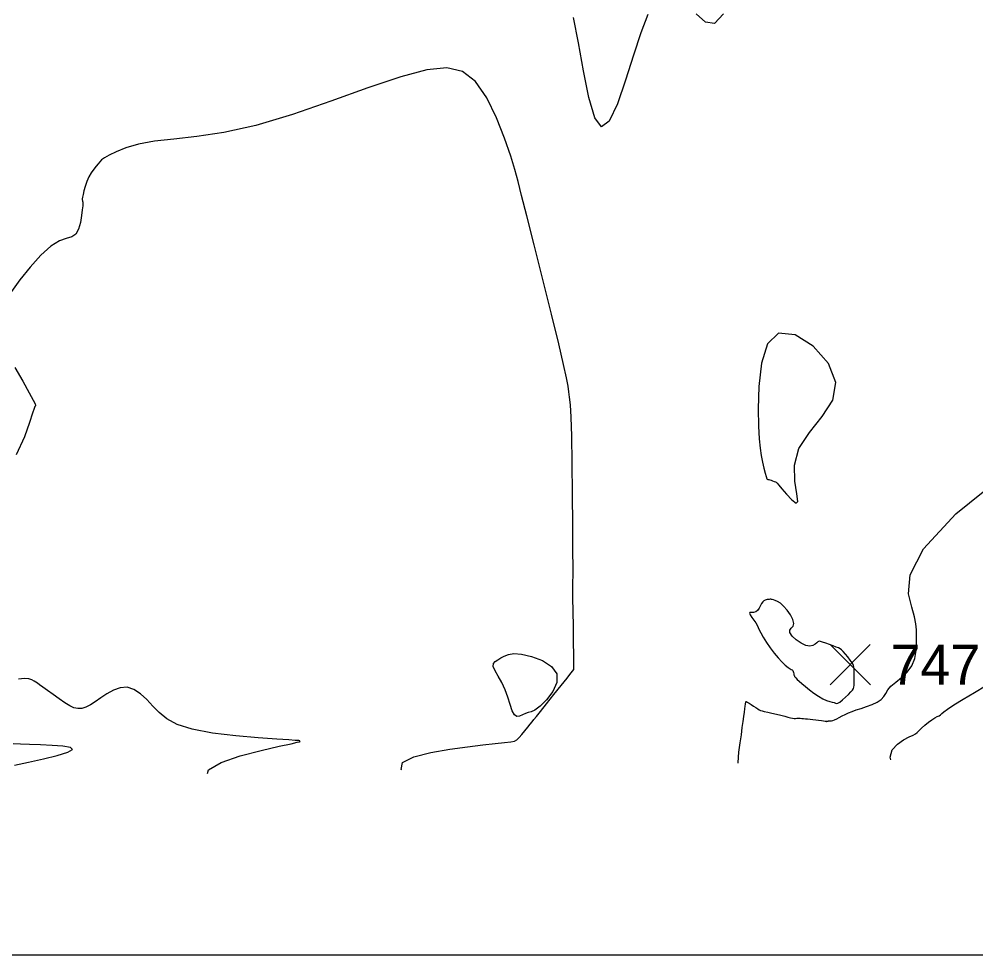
# Model space of a CAD drawing. Extents: x 2566142 to 2571431, y 418755 to 421584.
# Drawn here: x 2568478.9 to 2568835.3, y 418777.5 to 419126 of the extents above; entities that cross this region are included whole.
import ezdxf

# ---------------------------------------------------------------- set-up
doc = ezdxf.new("R2010")
doc.units = 0
for name, color, linetype in [('Contour_ADS_Major', 7, 'Continuous'), ('Contour_ADS_Minor', 7, 'Continuous'), ('Contour_ADS_Spot_Elevation', 7, 'Continuous'), ('Contour_ADS_State_Plane_Border', 7, 'Continuous')]:
    doc.layers.add(name, color=color, linetype=linetype)

# ---------------------------------------------------------------- blocks, each defined once
blk = doc.blocks.new('S750')
at = {"layer": 'Contour_ADS_Spot_Elevation'}
for p, q in [((-0.5, 0.498), (0.5, -0.498)), ((-0.498, -0.5), (0.498, 0.5))]:
    blk.add_line(p, q, dxfattribs=at)

msp = doc.modelspace()

# ---------------------------------------------------------------- linework, layer by layer
at = {"layer": 'Contour_ADS_Major'}
msp.add_lwpolyline([(2568477.19, 418848.2), (2568482.38, 418849.31), (2568487.94, 418850.54), (2568493.08, 418851.8), (2568496.98, 418852.98), (2568498.8, 418853.97), (2568498.01, 418854.69), (2568495.18, 418855.16), (2568491.15, 418855.47), (2568486.79, 418855.66), (2568482.81, 418855.81), (2568479.42, 418855.95), (2568476.7, 418856.09)], dxfattribs=at)
at = {"layer": 'Contour_ADS_Minor'}
for points in [[(2568713.02, 419127.71), (2568710.51, 419120.89), (2568707.78, 419112.58), (2568704.81, 419103.24), (2568701.72, 419094.43), (2568698.67, 419088.02), (2568695.84, 419085.87), (2568693.34, 419089.2), (2568691.13, 419096.77), (2568689.13, 419106.71), (2568687.25, 419117.14), (2568685.41, 419126.55)], [(2568741.27, 419127.97), (2568737.96, 419124.32), (2568734.53, 419124.89), (2568731.13, 419127.95)], [(2568621.43, 418846.45), (2568621.24, 418846.59), (2568621.73, 418849.14), (2568625.9, 418851.19), (2568632.28, 418852.81), (2568639.38, 418854.06), (2568645.93, 418855), (2568651.59, 418855.7), (2568656.22, 418856.19), (2568659.7, 418856.55), (2568661.99, 418856.82), (2568663.38, 418857.13), (2568664.29, 418857.61), (2568665.09, 418858.39), (2568666.09, 418859.54), (2568667.23, 418860.9), (2568668.35, 418862.28), (2568669.29, 418863.45), (2568669.99, 418864.31), (2568670.65, 418865.13), (2568671.6, 418866.3), (2568673.12, 418868.19), (2568675.39, 418871.03), (2568678.09, 418874.42), (2568680.78, 418877.79), (2568683.01, 418880.57), (2568684.43, 418882.35), (2568685.17, 418883.28), (2568685.45, 418883.64), (2568685.51, 418883.73), (2568685.52, 418883.85), (2568685.52, 418884.48), (2568685.51, 418886.08), (2568685.47, 418889.16), (2568685.41, 418893.95), (2568685.33, 418899.72), (2568685.25, 418905.5), (2568685.19, 418910.31), (2568685.15, 418913.44), (2568685.14, 418915.12), (2568685.14, 418915.89), (2568685.16, 418916.24), (2568685.19, 418916.74), (2568685.21, 418918.26), (2568685.22, 418921.69), (2568685.2, 418927.95), (2568685.14, 418937.5), (2568685.04, 418949.01), (2568684.9, 418960.68), (2568684.72, 418970.73), (2568684.5, 418977.8), (2568684.24, 418982.32), (2568683.96, 418985.17), (2568683.68, 418987.2), (2568683.36, 418989.29), (2568682.79, 418992.35), (2568681.72, 418997.32), (2568679.88, 419005.1), (2568677.15, 419016.16), (2568673.92, 419029.05), (2568670.68, 419041.89), (2568667.95, 419052.77), (2568666.08, 419060.35), (2568664.77, 419065.57), (2568663.57, 419069.93), (2568662.01, 419074.92), (2568659.73, 419081.6), (2568656.72, 419089.24), (2568653.07, 419096.67), (2568648.86, 419102.71), (2568644.08, 419106.42), (2568638.24, 419107.81), (2568630.75, 419107.09), (2568621.05, 419104.49), (2568608.83, 419100.35), (2568594.97, 419095.39), (2568580.67, 419090.44), (2568567.09, 419086.35), (2568555.2, 419083.71), (2568545.05, 419082.22), (2568536.47, 419081.34), (2568529.3, 419080.54), (2568523.4, 419079.4), (2568518.67, 419078.01), (2568515.02, 419076.57), (2568512.4, 419075.28), (2568510.68, 419074.31), (2568509.62, 419073.55), (2568508.93, 419072.87), (2568508.31, 419072.13), (2568507.56, 419071.22), (2568506.69, 419070.1), (2568505.77, 419068.77), (2568504.9, 419067.22), (2568504.14, 419065.48), (2568503.52, 419063.69), (2568503.04, 419062.02), (2568502.7, 419060.64), (2568502.5, 419059.67), (2568502.42, 419059.06), (2568502.42, 419058.69)], [(2568502.42, 419058.69), (2568502.45, 419058.46), (2568502.48, 419058.29), (2568502.51, 419058.14), (2568502.54, 419058.01), (2568502.58, 419057.88), (2568502.61, 419057.71), (2568502.61, 419057.32), (2568502.56, 419056.49), (2568502.43, 419055.02), (2568502.18, 419052.81), (2568501.74, 419050.22), (2568501.03, 419047.75), (2568499.96, 419045.87), (2568498.46, 419044.89), (2568496.46, 419044.29), (2568493.91, 419043.38), (2568490.75, 419041.46), (2568486.99, 419038.06), (2568483, 419033.65), (2568479.2, 419028.89), (2568476.03, 419024.49)], [(2568477.27, 418996.23), (2568480.21, 418991.12), (2568482.63, 418986.86), (2568484.13, 418984.12), (2568484.85, 418982.68), (2568485.04, 418982.09), (2568484.95, 418981.92), (2568484.78, 418981.73), (2568484.45, 418980.99), (2568483.81, 418979.18), (2568482.72, 418975.76), (2568480.92, 418970.41), (2568477.81, 418963.68)], [(2568813.11, 418898.58), (2568812.93, 418900.76), (2568812.42, 418903.38), (2568811.41, 418906.94), (2568810.16, 418911.94), (2568810.76, 418918.99), (2568815.8, 418928.71), (2568827.81, 418941.71), (2568848.18, 418958.1)], [(2568765.95, 418897.5), (2568765.96, 418898.41), (2568766.51, 418899.13), (2568767.17, 418899.89), (2568767.48, 418900.93), (2568767.12, 418902.41), (2568766.2, 418904.15), (2568764.96, 418905.89), (2568763.64, 418907.4), (2568762.44, 418908.46), (2568761.41, 418909.14), (2568760.56, 418909.52), (2568759.9, 418909.73), (2568759.43, 418909.84), (2568759.1, 418909.89), (2568758.84, 418909.91), (2568758.59, 418909.91), (2568758.28, 418909.9), (2568757.93, 418909.88), (2568757.55, 418909.84), (2568757.14, 418909.76), (2568756.73, 418909.63), (2568756.31, 418909.39), (2568755.88, 418908.99), (2568755.45, 418908.39), (2568755, 418907.55), (2568754.51, 418906.63), (2568753.94, 418905.8), (2568753.25, 418905.23), (2568752.45, 418905.04), (2568751.68, 418905.06), (2568751.1, 418905.06), (2568750.89, 418904.81), (2568751.17, 418904.16), (2568751.79, 418903.2), (2568752.56, 418902.13), (2568753.25, 418901.1), (2568753.75, 418900.25), (2568754.12, 418899.46), (2568754.55, 418898.56), (2568755.16, 418897.37), (2568756.1, 418895.77), (2568757.29, 418893.88), (2568758.67, 418891.87), (2568760.15, 418889.9), (2568761.63, 418888.13), (2568763.04, 418886.61), (2568764.29, 418885.39), (2568765.31, 418884.52), (2568766.04, 418884.01), (2568766.52, 418883.75), (2568766.83, 418883.59), (2568767.04, 418883.39), (2568767.2, 418883.06), (2568767.33, 418882.63), (2568767.44, 418882.19), (2568767.52, 418881.82), (2568767.58, 418881.59), (2568767.62, 418881.47), (2568767.65, 418881.42), (2568767.67, 418881.39), (2568767.69, 418881.32), (2568767.75, 418881.2), (2568767.92, 418880.98), (2568768.24, 418880.62), (2568768.76, 418880.1), (2568769.5, 418879.4), (2568770.49, 418878.52), (2568771.75, 418877.47), (2568773.28, 418876.25), (2568774.97, 418874.98), (2568776.68, 418873.79), (2568778.29, 418872.84), (2568779.68, 418872.21), (2568780.84, 418871.83), (2568781.77, 418871.61), (2568782.47, 418871.45), (2568782.98, 418871.27), (2568783.41, 418871.16), (2568783.89, 418871.25), (2568784.57, 418871.64), (2568785.53, 418872.42), (2568786.66, 418873.44), (2568787.77, 418874.51), (2568788.7, 418875.45), (2568789.32, 418876.13), (2568789.67, 418876.66), (2568789.84, 418877.22), (2568789.89, 418877.98), (2568789.91, 418879.07), (2568789.91, 418880.36), (2568789.91, 418881.7), (2568789.91, 418882.9), (2568789.92, 418883.85), (2568789.87, 418884.63), (2568789.66, 418885.38), (2568789.22, 418886.24), (2568788.5, 418887.29), (2568787.59, 418888.43), (2568786.66, 418889.54), (2568785.84, 418890.45)], [(2568746.68, 418848.95), (2568746.69, 418849.1), (2568747.03, 418852.95), (2568747.49, 418856.43), (2568747.91, 418859.49), (2568748.27, 418862.13), (2568748.57, 418864.39), (2568748.82, 418866.3), (2568749.03, 418867.88), (2568749.2, 418869.15), (2568749.34, 418870.13), (2568749.44, 418870.82), (2568749.5, 418871.25), (2568749.53, 418871.49), (2568749.56, 418871.6), (2568749.58, 418871.66), (2568749.61, 418871.73), (2568749.65, 418871.8), (2568749.69, 418871.86), (2568749.73, 418871.9), (2568749.77, 418871.89), (2568749.8, 418871.86), (2568749.83, 418871.81), (2568749.86, 418871.76), (2568749.9, 418871.71), (2568750.02, 418871.63), (2568750.28, 418871.47), (2568750.77, 418871.18), (2568751.51, 418870.73), (2568752.41, 418870.18), (2568753.31, 418869.63), (2568754.07, 418869.14), (2568754.61, 418868.8), (2568755.06, 418868.55), (2568755.61, 418868.34), (2568756.46, 418868.12), (2568757.73, 418867.84), (2568759.32, 418867.52), (2568761.01, 418867.16), (2568762.65, 418866.78), (2568764.06, 418866.41), (2568765.24, 418866.07), (2568766.21, 418865.79), (2568767, 418865.61), (2568767.63, 418865.55), (2568768.14, 418865.56), (2568768.57, 418865.62), (2568768.99, 418865.66), (2568769.41, 418865.67), (2568769.88, 418865.64), (2568770.42, 418865.58), (2568771.03, 418865.5), (2568771.75, 418865.43), (2568772.57, 418865.35), (2568773.49, 418865.25), (2568774.51, 418865.14), (2568775.6, 418865), (2568776.7, 418864.86), (2568777.71, 418864.72), (2568778.53, 418864.61), (2568779.11, 418864.53), (2568779.46, 418864.48), (2568779.67, 418864.46), (2568779.8, 418864.46), (2568779.9, 418864.47), (2568779.99, 418864.49), (2568780.07, 418864.52), (2568780.16, 418864.55), (2568780.27, 418864.58), (2568780.4, 418864.6), (2568780.58, 418864.61), (2568780.81, 418864.6), (2568781.1, 418864.6), (2568781.48, 418864.63), (2568781.98, 418864.74), (2568782.63, 418864.98), (2568783.43, 418865.38), (2568784.37, 418865.9), (2568785.44, 418866.48), (2568786.59, 418867.07), (2568787.83, 418867.62), (2568789.19, 418868.15), (2568790.73, 418868.7), (2568792.51, 418869.3), (2568794.53, 418869.98), (2568796.61, 418870.75), (2568798.53, 418871.62), (2568800.04, 418872.59), (2568801.02, 418873.67), (2568801.72, 418874.86), (2568802.48, 418876.15), (2568803.64, 418877.54), (2568805.42, 418879.06), (2568807.57, 418880.76), (2568809.71, 418882.75), (2568811.46, 418885.1), (2568812.53, 418887.85), (2568813.03, 418890.81), (2568813.17, 418893.73), (2568813.14, 418896.36), (2568813.11, 418898.58)], [(2568785.84, 418890.45), (2568785.23, 418891.07), (2568784.71, 418891.49), (2568784.11, 418891.8), (2568783.28, 418892.15), (2568782.1, 418892.6), (2568780.72, 418893.12), (2568779.34, 418893.62), (2568778.18, 418894.01), (2568777.39, 418894.23), (2568776.87, 418894.27), (2568776.46, 418894.11), (2568776.02, 418893.75), (2568775.4, 418893.23), (2568774.55, 418892.74), (2568773.41, 418892.49), (2568771.94, 418892.72), (2568770.15, 418893.57), (2568768.33, 418894.84), (2568766.81, 418896.24), (2568765.95, 418897.5), (2568765.95, 418897.5)], [(2568549.03, 418845), (2568549.48, 418846.35), (2568554.15, 418849.14), (2568561.24, 418851.6), (2568569.03, 418853.65), (2568575.79, 418855.17), (2568580.18, 418856.14), (2568582.48, 418856.66), (2568583.37, 418856.89), (2568583.52, 418856.98), (2568583.49, 418857.06), (2568583.4, 418857.15), (2568583.26, 418857.23), (2568583.08, 418857.29), (2568582.77, 418857.32), (2568581.76, 418857.38), (2568579.35, 418857.52), (2568574.88, 418857.81), (2568567.98, 418858.3), (2568559.58, 418859.05), (2568550.95, 418860.1), (2568543.36, 418861.52), (2568537.76, 418863.32), (2568533.86, 418865.43), (2568531.05, 418867.75), (2568528.74, 418870.18), (2568526.44, 418872.59), (2568524.05, 418874.73), (2568521.59, 418876.35), (2568519.08, 418877.16), (2568516.53, 418876.99), (2568514, 418876.07), (2568511.58, 418874.69), (2568509.32, 418873.16), (2568507.27, 418871.76), (2568505.43, 418870.6), (2568503.75, 418869.74), (2568502.21, 418869.25), (2568500.76, 418869.19), (2568499.31, 418869.54), (2568497.73, 418870.29), (2568495.91, 418871.41), (2568493.81, 418872.84), (2568491.59, 418874.43), (2568489.49, 418875.96), (2568487.75, 418877.24), (2568486.52, 418878.12), (2568485.68, 418878.69), (2568485.05, 418879.09), (2568484.43, 418879.45), (2568483.64, 418879.88), (2568482.52, 418880.24), (2568480.92, 418880.37), (2568478.68, 418880.12)], [(2568803.54, 418850.09), (2568803.33, 418851.07), (2568804.15, 418853.82), (2568806.04, 418855.95), (2568808.36, 418857.53), (2568810.48, 418858.64), (2568811.89, 418859.36), (2568812.75, 418859.87), (2568813.37, 418860.35), (2568814.07, 418860.99), (2568815.06, 418861.92), (2568816.29, 418863.01), (2568817.61, 418864.12), (2568818.87, 418865.08), (2568819.96, 418865.76), (2568820.85, 418866.23), (2568821.57, 418866.58), (2568822.14, 418866.91), (2568822.63, 418867.34), (2568823.35, 418867.99), (2568824.69, 418869.02), (2568827.02, 418870.56), (2568830.53, 418872.68), (2568834.7, 418875.17), (2568838.85, 418877.72)]]:
    msp.add_lwpolyline(points, dxfattribs=at)
for points in [[(2568757.14, 418955.61), (2568757.43, 418954.83), (2568757.65, 418954.49), (2568757.79, 418954.43), (2568757.88, 418954.49), (2568757.95, 418954.55), (2568758.03, 418954.55), (2568758.2, 418954.51), (2568758.5, 418954.4), (2568758.97, 418954.24), (2568759.54, 418954.03), (2568760.11, 418953.83), (2568760.58, 418953.66), (2568760.92, 418953.52), (2568761.28, 418953.2), (2568761.92, 418952.48), (2568763.05, 418951.11), (2568764.77, 418949.04), (2568766.7, 418946.96), (2568768.29, 418945.75), (2568769, 418946.29), (2568768.58, 418949.18), (2568767.8, 418953.94), (2568767.7, 418959.82), (2568769.33, 418966.05), (2568773.24, 418972.05), (2568778.07, 418977.95), (2568781.99, 418984.04), (2568783.16, 418990.64), (2568780.34, 418997.73), (2568774.67, 419004.15), (2568767.91, 419008.4), (2568761.79, 419009.01), (2568757.68, 419005.05), (2568755.41, 418997.8), (2568754.44, 418989.12), (2568754.22, 418980.84), (2568754.29, 418974.41), (2568754.52, 418969.72), (2568754.87, 418966.24), (2568755.31, 418963.45), (2568755.79, 418960.96), (2568756.28, 418958.75), (2568756.74, 418956.93), (2568757.14, 418955.61)], [(2568679.23, 418882.17), (2568679.22, 418878.92), (2568677.67, 418875.54), (2568675.33, 418872.45), (2568672.92, 418870.06), (2568671.03, 418868.65), (2568669.62, 418867.98), (2568668.5, 418867.7), (2568667.49, 418867.43), (2568666.42, 418866.93), (2568665.33, 418866.44), (2568664.29, 418866.31), (2568663.35, 418866.89), (2568662.55, 418868.43), (2568661.8, 418870.71), (2568660.98, 418873.42), (2568659.94, 418876.23), (2568658.64, 418878.88), (2568657.29, 418881.24), (2568656.16, 418883.25), (2568655.52, 418884.84), (2568655.57, 418885.99), (2568656.19, 418886.8), (2568657.19, 418887.43), (2568658.37, 418888.06), (2568659.62, 418888.76), (2568661.13, 418889.38), (2568663.18, 418889.72), (2568666.04, 418889.54), (2568669.8, 418888.67), (2568673.81, 418887.12), (2568677.24, 418884.94), (2568679.23, 418882.17)]]:
    msp.add_lwpolyline(points, close=True, dxfattribs=at)
at = {"layer": 'Contour_ADS_State_Plane_Border'}
msp.add_lwpolyline([(2566164.43, 418777.5), (2571407.81, 418777.5), (2571407.81, 421561.67), (2566164.43, 421561.67), (2566164.43, 418777.5)], close=True, dxfattribs=at)

# ---------------------------------------------------------------- block references
at = {"layer": 'Contour_ADS_Spot_Elevation', "xscale": 15, "yscale": 15}
msp.add_blockref('S750', (2568788.46, 418885.57), dxfattribs=at)

# ---------------------------------------------------------------- texts
at = {"layer": 'Contour_ADS_Spot_Elevation'}
msp.add_text('747.9', height=15, dxfattribs=at).set_placement((2568803.46, 418878.07))

doc.saveas('drawing.dxf')
